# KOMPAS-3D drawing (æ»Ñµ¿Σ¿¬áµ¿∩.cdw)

Referenced files: Спецификация.cdw
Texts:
  Тяга Спецификация
  Текст на чертеже
  Размерные надписи
  Шероховатость
  Линия-выноска #1
  Линия-выноска #2
  Линия-выноска #3
  Отклонения формы и база
  Заголовок таблицы
  Ячейка таблицы
  Стрелка вида
  Обозначение изменения
  Фигурная скобка
  Номер узла
  Марка координационной оси
  VRCB
  Выносная надпись
  Обозначение узла
  Марка/позиционное обозначение с линией-выноской
  Марка/позиционное обозначение на линии
  Марка/позиционное обозначение без линии-выноски
  Тяга
  ХХХХ.ХХ.ХХ.00 СБ
  Документация
  Сборочный чертеж.
  Детали
  Корпус
  Серьга
  Вилка
  Вкладыш
  Ось
  Кольцо
  ГОСТ 1477-93
  ГОСТ 1491-80
  Винт М4х8.58
  Винт 2М4х10.58
  Планка
  Стандартные изделия
Dimensions and other numbers on the sheet: 7; 4; 1:1; 1; 2; 3; 5; 6; 0; 8; 9; 10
